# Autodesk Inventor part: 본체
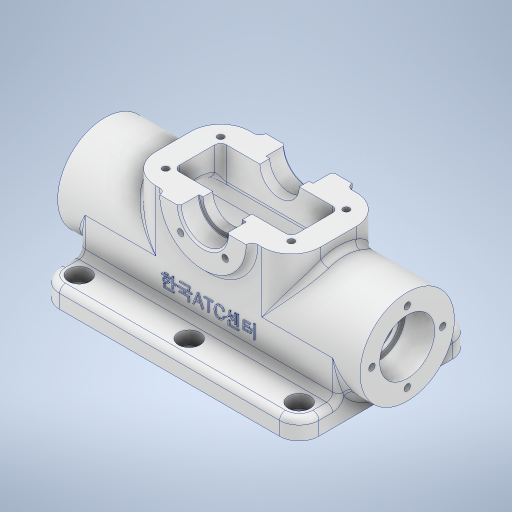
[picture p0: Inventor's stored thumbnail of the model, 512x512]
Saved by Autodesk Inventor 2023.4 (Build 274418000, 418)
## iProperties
Created: 2024-06
Part Number: 본체
Material: 알루미늄 6061
Document SubType Name: Modeling
Designer: user
Density: 2.7 g/cm^3
Appearance: 알루미늄 - 평지
Mass: 551.897 g
Surface Area: 613.714 cm^2
Volume: 204.406 cm^3
Author: user
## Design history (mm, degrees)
sketch "스케치1"
  geometry: L1 (66, 44)-(-66, 44); L2 (-66, 44)-(-66, -44); L3 (-66, -44)-(66, -44); L4 (66, -44)-(66, 44); L5 (66, 44)-(-66, -44); L6 (-66, 44)-(66, -44); 1 further point
  constraints: 12 end point, 2 midpoint, 2 parallel, 1 horizontal, 1 perpendicular
  dimensions: "d0" = 132 distance of L2.end L3.end; "d1" = 88 distance of L1.end L2.end
extrude "돌출1" new body sketch "스케치1" distance "d2" = 10; taper "d3" = 0 deg
sketch "스케치2"
  geometry: L1 (0, -44)-(0, 44) reference; C1 r 24 at (28, 0); 2 further points
  constraints: 1 centre point, 1 horizontal alignment, 1 midpoint
  dimensions: "d4" = 48 diameter of C1; "d5" = 28 distance from line of L1 C1.centre
extrude "돌출2" join sketch "스케치2" stored distance "d6" = 154; taper "d7" = 0 deg
sketch "스케치3"
  geometry: L1 (10, 44)-(10, 15.875) reference; L2 (28, -24)-(10, -24); L3 (10, -24)-(10, 24); L4 (10, 24)-(28, 24); L5 (28, 24)-(28, -24); A1 r 24 centre (28, 0) between (28, -24) and (10, 15.875) reference; A2 r 24 centre (28, 0) between (28, -24) and (10, 15.875) reference; 3 further points
  constraints: 8 end point, 2 parallel, 2 tangent, 1 horizontal, 1 perpendicular, 1 point on circle, 1 point on line
extrude "돌출3" join sketch "스케치3" stored distance "d8" = 132; taper "d9" = 0 deg
node "작업 평면1"
sketch "스케치4"
  geometry: L1 (108, 0)-(24, 0); L2 (24, 0)-(24, -48); L3 (24, -48)-(108, -48); L4 (108, -48)-(108, 0); L5 (132, -48)-(0, -48) reference; L6 (0, -48)-(-11, -48) reference; L7 (-11, -48)-(-11, 0) reference; L8 (-11, 0)-(0, 0) reference; L9 (0, 0)-(132, 0) reference; L10 (132, 0)-(143, 0) reference; L11 (143, 0)-(143, -48) reference; L12 (143, -48)-(132, -48) reference; 1 further point
  constraints: 8 end point, 2 parallel, 2 point on line, 1 horizontal, 1 perpendicular
  dimensions: "d10" = 84 distance between parallel lines of L2 L4; "d11" = 42 distance from line of point (66, -24) L2
extrude "돌출4" join sketch "스케치4" distance "d12" = 31; taper "d13" = 0 deg
sketch "스케치5"
  geometry: L1 (66, 0)-(-66, 0) reference; L2 (-66, 4)-(-77, 4) reference; L3 (-77, 4)-(-77, 52) reference; L4 (-77, 52)-(-42, 52) reference; L5 (-42, 52)-(-42, 59) reference; L6 (-42, 59)-(42, 59) reference; L7 (42, 59)-(42, 52) reference; L8 (42, 52)-(77, 52) reference; L9 (77, 52)-(77, 4) reference; L10 (77, 4)-(66, 4) reference; L11 (66, 4)-(66, 0) reference; L12 (66, 0)-(-66, 0) reference; L13 (-66, 0)-(-66, 4) reference; C1 r 22 at (0, 59); 4 further points
  constraints: 1 centre point, 1 midpoint, 1 vertical alignment
  dimensions: "d14" = 44 diameter of C1; "d15" = 59 distance from line of L1 C1.centre
extrude "돌출5" join sketch "스케치5" stored distance "d16" = 54; taper "d17" = 0 deg
sketch "스케치6"
  geometry: L1 (37, -27)-(59, -27) reference; L2 (47, -27)-(47, -17); L3 (47, -17)-(49, -17); L4 (49, -17)-(49, 17); L5 (49, 17)-(47, 17); L6 (47, 17)-(47, 27); L7 (59, 27)-(37, 27) reference; L8 (59, -27)-(59, 27); 1 further point
  constraints: 12 end point, 4 point on line, 3 perpendicular, 2 vertical
  dimensions: "d18" = 24 diameter of L2 L8; "d19" = 20 diameter of L4 L8; "d20" = 10 distance of L5.end L6.end; "d21" = 10 distance of L2.start L2.end
revolve "회전1" sketch "스케치6" stored, may be unused: angle "d22" = 90 deg
sketch "스케치7"
  geometry: L1 (36, -12)-(96, -12); L2 (96, -12)-(96, -36); L3 (96, -36)-(36, -36); L4 (36, -36)-(36, -12); L5 (36, -12)-(96, -36); L6 (96, -12)-(36, -36); 1 further point
  constraints: 12 end point, 2 midpoint, 2 parallel, 1 horizontal, 1 perpendicular
  dimensions: "d23" = 60 distance between parallel lines of L4 L2; "d24" = 24 distance of L3.end L1.start
extrude "돌출6" cut sketch "스케치7" extent not by distance; stored distance "d25" = 0; taper "d26" = 0 deg
sketch "스케치8"
  geometry: L1 (0, 44)-(0, -44) reference; L2 (28, -18)-(0, -18); L3 (28, 18)-(0, 18); A1 r 18 centre (28, 0) between (28, -18) and (28, 18); 2 further points
  constraints: 4 end point, 2 point on circle, 2 point on line, 2 tangent, 1 centre point, 1 horizontal, 1 horizontal alignment, 1 midpoint, 1 perpendicular
  dimensions: "d27" = 36 diameter of A1; "d28" = 28 distance from line of L1 A1.centre
extrude "돌출7" cut sketch "스케치8" stored distance "d29" = 120; taper "d30" = 0 deg
sketch "스케치9"
  geometry: L1 (-77, 52)-(-77, 4) reference; L2 (-77, 42)-(-62, 42); L3 (-62, 42)-(-62, 39); L4 (-62, 39)-(-60, 39); L5 (-60, 46)-(-60, 28) reference; L6 (77, 4)-(77, 52) reference; L7 (77, 42)-(62, 42); L8 (62, 42)-(62, 39); L9 (62, 39)-(60, 39); L10 (77, 4)-(66, 4) reference; L11 (66, 4)-(66, 0) reference; L12 (66, 0)-(60, 0) reference; L13 (60, 0)-(60, 46) reference; L14 (60, 46)-(30, 46) reference; L15 (30, 46)-(30, 59) reference; L16 (30, 59)-(42, 59) reference; L17 (42, 59)-(42, 52) reference; L18 (42, 52)-(77, 52) reference; L19 (77, 52)-(77, 4) reference; L20 (-66, 4)-(-77, 4) reference; L21 (-77, 4)-(-77, 52) reference; L22 (-77, 52)-(-42, 52) reference; L23 (-42, 52)-(-42, 59) reference; L24 (-42, 59)-(-30, 59) reference; L25 (-30, 59)-(-30, 46) reference; L26 (-30, 46)-(-60, 46) reference; L27 (-60, 46)-(-60, 0) reference; L28 (-60, 0)-(-66, 0) reference; L29 (-66, 0)-(-66, 4) reference; L30 (-77, 28)-(77, 28); 5 further points
  constraints: 14 end point, 6 point on line, 2 horizontal, 2 midpoint, 2 perpendicular, 1 vertical
  dimensions: "d31" = 28 diameter of L7 L30; "d32" = 22 diameter of L9 L30; "d33" = 28 diameter of L2 L30; "d34" = 15 distance of L2.start L2.end; "d35" = 15 distance of L7.start L7.end
revolve "회전2" sketch "스케치9" stored, may be unused: angle "d36" = 90 deg
fillet "모깎기1" dims "d37" = 0.3
fillet "모깎기2" dims "d38" = 15
fillet "모깎기3" dims "d39" = 3
sketch "스케치10"
  geometry: L1 (0, -10)-(132, -10) reference; L2 (41.419, 13.539)-(91.194, 13.539); L3 (91.194, 13.539)-(91.194, 6.334); L4 (91.194, 6.334)-(41.419, 6.334); L5 (41.419, 6.334)-(41.419, 13.539); 3 further points
  constraints: 1 midpoint, 1 vertical alignment, 2 other
  dimensions: "d40" = 20 distance from line of L1 point (66, 10)
feature "엠보싱1" sketch "스케치10" dims "d41" = 0.5, "d42" = 0
sketch "스케치11"
  geometry: C1 r 14 at (0, 0) reference; A1 r 18 centre (0, 0) between (-12, 13.416) and (12, 13.416); A2 r 18 centre (0, 0) between (12, 13.416) and (-12, 13.416) reference; 2 further points
  constraints: 1 centre point, 1 coincident, 1 point on circle
  dimensions: "d43" = 36 diameter of A1
hole "구멍1" sketch "스케치11" at (0, 18) diameter "d44" = 3.242; stored, may be unused: countersink angle "d48" = 90 deg, drill point angle "d50" = 118 deg; dims "d45" = 8, "d46" = 4, "d47" = 2, "d49" = 10
fillet "모깎기4" dims "d54" = 10
fillet "모깎기5" dims "d55" = 3
fillet "모깎기6" dims "d56" = 3
fillet "모깎기7" dims "d57" = 3
fillet "모깎기8" dims "d58" = 3
fillet "모깎기9" dims "d59" = 3
sketch "스케치12"
  geometry: L1 (77.7, -41)-(76, -41) reference; L2 (76, -41)-(76, -36) reference; L3 (76, -36)-(93, -36) reference; L4 (96, -33)-(96, -15) reference; L5 (93, -12)-(76, -12) reference; L6 (76, -12)-(76, -7) reference; L7 (76, -7)-(77.7, -7) reference; L8 (78, -6.7)-(78, 3) reference; L9 (78, 3)-(88, 3) reference; L10 (88, 3)-(88, 0) reference; L11 (88, 0)-(93, 0) reference; L12 (108, -15)-(108, -33) reference; L13 (93, -48)-(88, -48) reference; L14 (88, -48)-(88, -51) reference; L15 (88, -51)-(78, -51) reference; L16 (78, -51)-(78, -41.3) reference; L17 (54, -41.3)-(54, -51) reference; L18 (54, -51)-(44, -51) reference; L19 (44, -51)-(44, -48) reference; L20 (44, -48)-(39, -48) reference; L21 (24, -33)-(24, -15) reference; L22 (39, 0)-(44, 0) reference; L23 (44, 0)-(44, 3) reference; L24 (44, 3)-(54, 3) reference; L25 (54, 3)-(54, -6.7) reference; L26 (54.3, -7)-(56, -7) reference; L27 (56, -7)-(56, -12) reference; L28 (56, -12)-(39, -12) reference; L29 (36, -15)-(36, -33) reference; L30 (39, -36)-(56, -36) reference; L31 (56, -36)-(56, -41) reference; L32 (56, -41)-(54.3, -41) reference; L33 (98, -38)-(34, -38); L34 (34, -38)-(34, -10); L35 (34, -10)-(98, -10); L36 (98, -10)-(98, -38); A1 r 0.3 centre (77.7, -41.3) between (78, -41.3) and (77.7, -41) reference; A2 r 3 centre (93, -33) between (93, -36) and (96, -33) reference; A3 r 3 centre (93, -15) between (96, -15) and (93, -12) reference; A4 r 0.3 centre (77.7, -6.7) between (77.7, -7) and (78, -6.7) reference; A5 r 15 centre (93, -15) between (108, -15) and (93, 0) reference; A6 r 15 centre (93, -33) between (93, -48) and (108, -33) reference; A7 r 0.3 centre (54.3, -41.3) between (54.3, -41) and (54, -41.3) reference; A8 r 15 centre (39, -33) between (24, -33) and (39, -48) reference; A9 r 15 centre (39, -15) between (39, 0) and (24, -15) reference; A10 r 0.3 centre (54.3, -6.7) between (54, -6.7) and (54.3, -7) reference; A11 r 3 centre (39, -15) between (39, -12) and (36, -15) reference; A12 r 3 centre (39, -33) between (36, -33) and (39, -36) reference; 1 further point
  constraints: 8 end point, 2 parallel, 1 horizontal, 1 perpendicular
  dimensions: "d60" = 64 distance of L33.start L33.end; "d61" = 28 distance of L33.end L34.end; "d62" = 32 distance from line of point (66, -24) L34; "d63" = 14 distance from line of L35 point (66, -24)
hole "구멍2" sketch "스케치12" at (98, -38), (34, -38), (34, -10), (98, -10) diameter "d64" = 3.242; stored, may be unused: countersink angle "d68" = 90 deg, drill point angle "d70" = 118 deg; dims "d65" = 8, "d66" = 4, "d67" = 2, "d69" = 10
sketch "스케치13" dims "d71" = 32
  geometry: L1 (0, 59)-(0, 37); L2 (0, 59)-(-11.314, 47.686); A1 r 10 centre (0, 59) between (-10, 59) and (10, 59) reference; A2 r 22 centre (0, 59) between (-22, 59) and (22, 59) reference; 2 further points
  constraints: 4 end point, 1 coincident, 1 point on circle, 1 vertical, 3 other
  dimensions: "d72" = 45 deg angle of L1 L2
hole "구멍3" sketch "스케치13" at (-11.314, 47.686) diameter "d73" = 3.242; stored, may be unused: countersink angle "d77" = 90 deg, drill point angle "d79" = 118 deg; dims "d74" = 8, "d75" = 4, "d76" = 2, "d78" = 10
fillet "모깎기10" dims "d83" = 3
fillet "모깎기11" dims "d84" = 3
sketch "스케치14"
  geometry: L1 (56, -34)-(-56, -34); L2 (-56, -34)-(-56, 34); L3 (-56, 34)-(56, 34); L4 (56, 34)-(56, -34); L5 (-60, 15)-(-60, -15) reference; L6 (-57, -18)-(57, -18) reference; L7 (60, -15)-(60, 15) reference; L8 (57, 18)-(-57, 18) reference; L9 (-66.026, 0)-(-67, 1.621) reference; L10 (-67, 1.621)-(-77, 1.621) reference; L11 (-77, 1.621)-(-77, 15.875) reference; L12 (-77, 15.875)-(-69, 15.875) reference; L13 (-66, 20.125)-(-66, 21.804) reference; L14 (-63, 34)-(-63, 27) reference; L15 (56, 41)-(-56, 41) reference; L16 (63, 27)-(63, 34) reference; L17 (66, 21.804)-(66, 20.125) reference; L18 (69, 15.875)-(77, 15.875) reference; L19 (77, 15.875)-(77, 1.621) reference; L20 (77, 1.621)-(67, 1.621) reference; L21 (67, 1.621)-(66.026, 0) reference; L22 (66.026, 0)-(67, -1.621) reference; L23 (67, -1.621)-(77, -1.621) reference; L24 (77, -1.621)-(77, -15.875) reference; L25 (77, -15.875)-(69, -15.875) reference; L26 (66, -20.125)-(66, -21.804) reference; L27 (63, -34)-(63, -27) reference; L28 (-56, -41)-(56, -41) reference; L29 (-63, -27)-(-63, -34) reference; L30 (-66, -21.804)-(-66, -20.125) reference; L31 (-69, -15.875)-(-77, -15.875) reference; L32 (-77, -15.875)-(-77, -1.621) reference; L33 (-77, -1.621)-(-67, -1.621) reference; L34 (-67, -1.621)-(-66.026, 0) reference; L35 (63, 27)-(-63, 27) reference; L36 (-63, -27)-(63, -27) reference; A1 r 7 centre (56, -34) between (56, -41) and (63, -34) reference; A2 r 7 centre (-56, 34) between (-56, 41) and (-63, 34) reference; A3 r 3 centre (-57, 15) between (-57, 18) and (-60, 15) reference; A4 r 3 centre (-57, -15) between (-60, -15) and (-57, -18) reference; A5 r 3 centre (57, -15) between (57, -18) and (60, -15) reference; A6 r 3 centre (57, 15) between (60, 15) and (57, 18) reference; A7 r 7 centre (-56, 34) between (-56, 41) and (-63, 34) reference; A8 r 7 centre (56, 34) between (63, 34) and (56, 41) reference; A9 r 7 centre (56, -34) between (56, -41) and (63, -34) reference; A10 r 7 centre (-56, -34) between (-63, -34) and (-56, -41) reference; 3 further points
  constraints: 8 end point, 2 midpoint, 2 parallel, 1 horizontal, 1 perpendicular, 8 other
hole "구멍4" sketch "스케치14" at (0, -34), (0, 34), (-56, 34), (-56, -34), (56, -34), (56, 34) diameter "d85" = 6.6; stored, may be unused: countersink angle "d89" = 90 deg, drill point angle "d91" = 118 deg; dims "d86" = 8, "d87" = 11, "d88" = 6.6, "d90" = 10
chamfer "모따기1" distance "d92" = 1; stored, may be unused: second distance "d93" = 2, angle "d94" = 45 deg
node "솔리드1"
pattern_circular "원형 패턴1" dims angle "d52" = 360 deg
mirror "미러1"
pattern_circular "원형 패턴2" dims angle "d81" = 360 deg
mirror "미러2"
node "절단 모서리 투영1"
node "절단 모서리 투영2"
node "절단 모서리 투영3"
node "절단 모서리 투영4"
node "절단 모서리 투영5"
feature "A9D066F2-1C7D-4E18-AEED-F7BC21143FA4" dims "d85" = 6.6, "d86" = 8, "d87" = 11, "d88" = 6.6, "d89" = 90 deg, "d90" = 10, "d91" = 118 deg
